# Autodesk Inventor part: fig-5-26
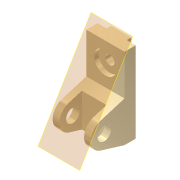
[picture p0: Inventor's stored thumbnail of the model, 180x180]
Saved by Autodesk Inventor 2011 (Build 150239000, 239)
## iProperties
Shininess: 65.0
Angle Display Precision: 2
Document Length Units: 11269
Document Angle Units: 11279
Document Time Units: 11290
Document Mass Units: 11283
Document Length Units Precision: 3
Document Angle Units Precision: 2
Compacted: False
Created: 2001-11
Part Number: fig-5-26
Document SubType Name: Modeling
Designer: Renu Muthoo
Density: 1 g/cm^3
Density: 0.0
Volumn: 0.0
Area: 0.0
PropertySet Name: Model Information
Control State: 0
Master: False
Checked Out: False
Author: Renu Muthoo
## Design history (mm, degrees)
node "Sketch1"
sketch "Sketch2"
  geometry: L1 (33.257, 104.664)-(33.257, -75.336); L2 (33.257, -75.336)-(8.257, -75.336); L3 (8.257, -75.336)-(-45.451, -59.045); L4 (-45.451, -1.628)-(8.257, 14.664); L5 (8.257, 14.664)-(8.257, 104.664); L6 (8.257, 104.664)-(33.257, 104.664); C1 r 15 at (-36.743, -30.336); A1 r 30 centre (-36.743, -30.336) between (-45.451, -1.628) and (-45.451, -59.045)
  constraints: 12 end point, 2 centre point, 2 equal length, 2 parallel, 2 point on circle, 2 tangent, 1 coincident, 1 perpendicular, 1 vertical
  dimensions: "d0" = 180 distance of L1.start L1.end; "d1" = 30 radius of A1; "d2" = 25 distance of L5.end L1.start; "d3" = 45 distance from line of L2 A1.centre; "d4" = 70 distance from line of L1 A1.centre; "d5" = 30 diameter of C1
extrude "Extrusion1" new body sketch "Sketch2" distance "d6" = 85; taper "d7" = 0 deg
workplane "Work Plane1"
sketch "Sketch3"
  geometry: L1 (15, 62.364)-(70, 62.364); L2 (70, 62.364)-(70, -52.386); L3 (70, -52.386)-(15, -52.386); L4 (15, -52.386)-(15, 62.364); L5 (0, -45)-(0, -28.708) reference
  constraints: 8 end point, 2 parallel, 1 horizontal, 1 perpendicular
  dimensions: "d8" = 55 distance of L1.start L1.end; "d9" = 15 distance between parallel lines of L5 L4
extrude "Extrusion2" cut sketch "Sketch3" distance "d10" = 50; taper "d11" = 0 deg
sketch "Sketch4"
  geometry: L1 (0, 25)-(85, 25) reference; L2 (0, 0)-(0, 25) reference; L3 (20, 25)-(65, 25); L4 (65, 25)-(65, 35); L5 (65, 35)-(20, 35); L6 (20, 35)-(20, 25)
  constraints: 8 end point, 2 parallel, 1 horizontal, 1 perpendicular, 1 point on line
  dimensions: "d12" = 45 distance of L4.end L5.end; "d13" = 10 distance of L3.end L4.end; "d14" = 20 distance between parallel lines of L2 L6
extrude "Extrusion3" join sketch "Sketch4" stored distance "d15" = 50; taper "d16" = 0 deg
sketch "Sketch5"
  geometry: L1 (85, 0)-(85, 90) reference; L2 (0, 90)-(85, 90) reference; 1 further point
  dimensions: "d17" = 42 distance from line of L2 point (42.5, 48); "d18" = 42.5 distance from line of L1 point (42.5, 48)
hole "Hole1" sketch "Sketch5" at (42.5, 48) diameter "d19" = 20; stored, may be unused: countersink angle "d23" = 82 deg, drill point angle "d25" = 118 deg; dims "d20" = 6, "d21" = 50, "d22" = 10, "d24" = 8
workplane "Work Plane12"
body "Solid1"
